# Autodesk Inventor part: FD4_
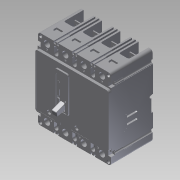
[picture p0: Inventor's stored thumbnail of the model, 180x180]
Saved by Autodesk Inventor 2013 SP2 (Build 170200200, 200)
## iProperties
Created: 2014-08
Part Number: FD4_
Material: Generic
Document SubType Name: Modeling
Designer: DM/JS
Density: 1 g/cm^3
Description: TYPE FD THERMAL MAGNETIC CIRCUIT BREAKERS FOUR POLE, SERIES C
Translation Standard: STEP AP214IS
FileName: Y:\ECO-062745\WIP\New\FD4_.stp
PreProcessor: Autodesk Inventor 2012
PostProcessor: Build: 219, Release: 2012 SP2 - Date: Fri 04/27/2012
Sent Units: inch
Uncertainty: 0.00039370078740199997
MXEDIT: false
MXINVTNRV: INV Versioned Component|FD4_|003.0
Author: DM/JS
Revision Number: 003
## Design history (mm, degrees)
node "FD4_"
node "L1"
node "L2"
node "L3"
node "L4"
node "T1"
node "T2"
node "T3"
node "T4"
body "Solid1"
node "Base1"
